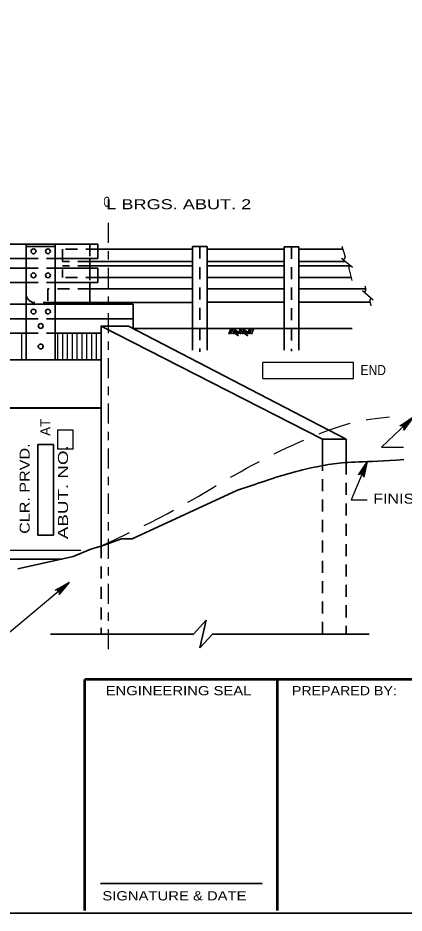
# Model space of a CAD drawing. Extents: x -11 to 79, y -154 to 0.
# Drawn here: x 11.68 to 16.3, y -43.25 to -32.54 of the extents above; entities that cross this region are included whole.
import ezdxf
from ezdxf.enums import TextEntityAlignment as Align

# ---------------------------------------------------------------- set-up
doc = ezdxf.new("R2010")
doc.units = 0
doc.header["$LTSCALE"] = 0.048
doc.linetypes.add('DOT_DASHED', pattern=[7.7, 5, -1.2, 0.3, -1.2])
doc.linetypes.add('MEDIUM_DASHED', pattern=[4.5, 3, -1.5])
for name, color, linetype, lineweight in [('1', 7, 'Continuous', 25), ('10', 7, 'Continuous', 40), ('3', 7, 'Continuous', 25), ('4', 7, 'Continuous', 25), ('5', 7, 'Continuous', 25), ('8', 7, 'Continuous', 35)]:
    doc.layers.add(name, color=color, linetype=linetype, lineweight=lineweight)

msp = doc.modelspace()

# ---------------------------------------------------------------- hatches: boundary and pattern name
at = {"layer": '3'}
msp.add_hatch(color=256, dxfattribs=at).paths.add_polyline_path([(15.79492, -37.95158), (15.83125, -37.96675), (15.85858, -37.85017)])
at = {"layer": '4'}
msp.add_hatch(color=256, dxfattribs=at).paths.add_polyline_path([(12.18967, -39.35475), (12.21492, -39.385), (12.293, -39.29417)])

# ---------------------------------------------------------------- linework, layer by layer
at = {"layer": '1', "lineweight": 35}
msp.add_lwpolyline([(1.75, -43.25), (33.25, -43.25), (33.25, -22.75), (1.75, -22.75)], close=True, dxfattribs=at)
at = {"layer": '3', "lineweight": 35}
for p, q in [((5.56042, -35.24708), (12.63733, -35.24708)), ((11.78058, -35.24708), (11.78058, -36.63125)), ((11.78058, -35.27592), (12.12658, -35.27592)), ((12.12658, -35.24708), (12.12658, -36.63125)), ((12.63733, -35.24708), (12.63733, -35.42008)), ((12.63733, -35.30808), (13.77008, -35.30808)), ((13.77008, -35.27758), (13.94308, -35.27758)), ((13.77008, -36.25633), (13.77008, -35.27758)), ((13.94308, -36.25633), (13.94308, -35.27758)), ((13.94308, -35.3095), (14.86583, -35.3095)), ((14.86583, -35.28067), (15.03883, -35.28067)), ((14.86583, -36.25633), (14.86583, -35.28067)), ((15.03883, -36.25633), (15.03883, -35.28067)), ((15.03883, -35.3095), (15.565, -35.3095)), ((10.22342, -35.42008), (11.78058, -35.42008)), ((12.12658, -35.42008), (12.63733, -35.42008)), ((12.54208, -35.42008), (12.54208, -35.5355)), ((10.22342, -35.5355), (11.78058, -35.5355)), ((12.12658, -35.5355), (12.63733, -35.5355)), ((12.54208, -35.45408), (13.77008, -35.45408)), ((12.54208, -35.50617), (13.77008, -35.50617)), ((12.63733, -35.5355), (12.63733, -35.7085)), ((13.94308, -35.45408), (14.86583, -35.45408)), ((13.94308, -35.50617), (14.86583, -35.50617)), ((15.03883, -35.45408), (15.59783, -35.45408)), ((15.03883, -35.50617), (15.65983, -35.50617)), ((12.63733, -35.6475), (13.77008, -35.6475)), ((13.94308, -35.6475), (14.86583, -35.6475)), ((15.03883, -35.6475), (15.666, -35.6475)), ((10.22342, -35.7085), (11.78058, -35.7085)), ((12.12658, -35.7085), (12.63733, -35.7085)), ((12.54208, -35.7085), (12.54208, -35.947)), ((12.54208, -35.78417), (13.77008, -35.78417)), ((13.94308, -35.78417), (14.86583, -35.78417)), ((15.03883, -35.78417), (15.84225, -35.78417)), ((10.22342, -35.968), (11.78058, -35.968)), ((11.78058, -35.968), (12.12658, -35.968)), ((12.12642, -35.947), (13.77008, -35.947)), ((12.12658, -35.968), (13.05858, -35.968)), ((13.05858, -36.25633), (13.05858, -35.968)), ((14.86583, -35.94242), (13.94308, -35.94242)), ((15.89208, -35.94242), (15.03883, -35.94242)), ((10.22342, -36.141), (11.78058, -36.141)), ((12.12658, -36.141), (13.05858, -36.141)), ((12.67467, -36.2275), (15.32283, -37.58275)), ((13.00317, -36.2275), (15.60825, -37.58275)), ((13.05858, -36.25633), (15.6805, -36.25633)), ((13.77008, -36.25633), (13.77008, -36.51583)), ((13.94308, -36.25633), (13.94308, -36.51583)), ((14.22942, -36.25633), (14.20275, -36.32658)), ((14.25133, -36.256), (14.22467, -36.32625)), ((14.27683, -36.25558), (14.25017, -36.32583)), ((14.265, -36.2865), (14.31667, -36.32225)), ((14.2715, -36.26933), (14.32308, -36.30517)), ((14.34192, -36.25558), (14.31567, -36.32483)), ((14.36383, -36.25542), (14.33758, -36.32442)), ((14.38917, -36.25517), (14.36308, -36.32408)), ((14.37742, -36.28608), (14.429, -36.32183)), ((14.38383, -36.26892), (14.4355, -36.30475)), ((14.45433, -36.25517), (14.42808, -36.32442)), ((14.47617, -36.255), (14.45, -36.32408)), ((14.50158, -36.25483), (14.4755, -36.32367)), ((14.86583, -36.25633), (14.86583, -36.51583)), ((15.03883, -36.25633), (15.03883, -36.51583)), ((10.22342, -36.314), (11.78058, -36.314)), ((12.12658, -36.314), (12.67467, -36.314)), ((12.67467, -36.4005), (12.67467, -38.86058)), ((14.25817, -36.30442), (14.31817, -36.346)), ((14.37058, -36.304), (14.43058, -36.34558)), ((5.52325, -36.63125), (12.67467, -36.63125)), ((15.32283, -37.58275), (15.60825, -37.58275)), ((15.32283, -37.89667), (15.32283, -37.58275)), ((15.60825, -37.58275), (15.60825, -37.86058)), ((14.30883, -38.19208), (13.04533, -38.77158)), ((13.04533, -38.77158), (12.91933, -38.77467)), ((5.77742, -39.016), (12.20667, -39.016)), ((13.77908, -39.91158), (13.93283, -39.74475)), ((13.93283, -39.74475), (13.85583, -40.0785)), ((12.07175, -39.91158), (13.77908, -39.91158)), ((13.85583, -40.0785), (14.00958, -39.91158)), ((14.00958, -39.91158), (15.88267, -39.91158))]:
    msp.add_line(p, q, dxfattribs=at)
at = {"layer": '3', "linetype": 'MEDIUM_DASHED', "lineweight": 35}
for p, q in [((12.63733, -35.30808), (12.21333, -35.30808)), ((12.21333, -35.30808), (12.21333, -35.6475)), ((12.54208, -35.24708), (12.54208, -35.42008)), ((13.85658, -35.27758), (13.85658, -36.53767)), ((14.95233, -35.28067), (14.95233, -36.52675)), ((11.78058, -35.42008), (12.12658, -35.42008)), ((11.78058, -35.5355), (12.12658, -35.5355)), ((12.54208, -35.45408), (12.21333, -35.45408)), ((12.54208, -35.50617), (12.21333, -35.50617)), ((12.54208, -35.5355), (12.54208, -35.7085)), ((12.63733, -35.6475), (12.21333, -35.6475)), ((11.78058, -35.7085), (12.12658, -35.7085)), ((12.12675, -35.947), (11.86333, -35.947)), ((11.78058, -36.141), (12.12658, -36.141)), ((11.78058, -36.314), (12.12658, -36.314)), ((15.32283, -39.91158), (15.32283, -37.89667)), ((15.60825, -37.86058), (15.60825, -39.91158)), ((12.67467, -38.86058), (12.67467, -39.91158))]:
    msp.add_line(p, q, dxfattribs=at)
at = {"layer": '3'}
for p, q in [((15.55342, -35.2735), (15.594, -35.39958)), ((15.55133, -35.41508), (15.68192, -35.52467)), ((15.63867, -35.53825), (15.67483, -35.68283)), ((15.83083, -35.74875), (15.84358, -35.78842)), ((15.80092, -35.80392), (15.9315, -35.9135)), ((15.88825, -35.92708), (15.90333, -35.9875)), ((5.52325, -36.63117), (12.67467, -36.63117)), ((16.40917, -37.31892), (16.02983, -37.67617)), ((16.02983, -37.67617), (16.29375, -37.67617)), ((15.85858, -37.85017), (15.66825, -38.30592)), ((15.66825, -38.30592), (15.85883, -38.30592))]:
    msp.add_line(p, q, dxfattribs=at)
at = {"layer": '3', "lineweight": 40}
msp.add_line((5.52325, -37.20783), (12.67467, -37.20783), dxfattribs=at)
at = {"layer": '3', "linetype": 'MEDIUM_DASHED', "lineweight": 35}
msp.add_lwpolyline([(12.54208, -35.78417), (12.0395, -35.78417), (12.0395, -35.947)], dxfattribs=at)
at = {"layer": '3', "lineweight": 35}
msp.add_lwpolyline([(12.67467, -36.4005), (12.67467, -36.2275), (13.00317, -36.2275)], dxfattribs=at)
at = {"layer": '3'}
msp.add_lwpolyline([(15.79492, -37.95158), (15.83125, -37.96675), (15.85858, -37.85017)], close=True, dxfattribs=at)
at = {"layer": '3', "lineweight": 35}
for centre in [(11.867, -35.33359), (12.04002, -35.33359), (11.867, -35.62194), (12.04002, -35.62194), (11.86699, -36.05451), (12.04, -36.05451), (11.9535, -36.22691), (11.95353, -36.472)]:
    msp.add_circle(centre, 0.02883, dxfattribs=at)
at = {"layer": '3'}
msp.add_circle((11.95353, -36.47195), 0.02883, dxfattribs=at)
for centre, start, end in [((15.57373, -35.40603), 227.85042, 17.85042), ((15.65947, -35.53355), 49.98318, 192.52183), ((15.65949, -35.5336), 49.98318, 49.99719), ((15.82331, -35.79486), 227.85042, 17.85042), ((15.90906, -35.92238), 49.98318, 192.52183), ((15.90907, -35.92243), 49.98318, 49.99719)]:
    msp.add_arc(centre, 0.02131, start, end, dxfattribs=at)
at = {"layer": '3', "linetype": 'MEDIUM_DASHED', "lineweight": 35}
msp.add_arc((11.89545, -35.83358), 0.1179, 193.19618, 254.16171, dxfattribs=at)
at = {"layer": '3', "lineweight": 35}
msp.add_open_spline([(14.30883, -38.19208), (14.62, -38.08475), (14.90592, -37.99158), (15.19175, -37.92175), (15.46175, -37.86933), (15.71583, -37.85192), (16.05733, -37.84608), (16.29558, -37.82275)], degree=3, dxfattribs=at)
at = {"layer": '4', "linetype": 'DOT_DASHED'}
msp.add_line((12.76092, -34.99267), (12.76092, -40.16842), dxfattribs=at)
at = {"layer": '4'}
for p, q in [((14.60825, -36.85342), (14.60825, -36.66525)), ((12.15275, -37.4725), (12.15275, -37.70242)), ((12.34092, -37.4725), (12.15275, -37.4725)), ((12.34092, -37.70242), (12.34092, -37.4725)), ((12.34092, -37.70242), (12.15275, -37.70242)), ((11.19925, -38.91042), (12.43233, -38.91042))]:
    msp.add_line(p, q, dxfattribs=at)
at = {"layer": '4', "lineweight": 35}
for p, q in [((11.91892, -37.64283), (11.91892, -38.72875)), ((12.10717, -37.64283), (11.91892, -37.64283)), ((12.10717, -38.72875), (12.10717, -37.64283)), ((12.10717, -38.72875), (11.91892, -38.72875)), ((14.60183, -42.89675), (12.66708, -42.89675))]:
    msp.add_line(p, q, dxfattribs=at)
at = {"layer": '4', "lineweight": 53}
for p, q in [((12.48275, -43.21967), (12.48275, -40.45567)), ((18.01075, -40.45567), (12.48275, -40.45567)), ((14.78617, -43.21967), (14.78617, -40.45567))]:
    msp.add_line(p, q, dxfattribs=at)
at = {"layer": '4'}
for points in [[(14.60825, -36.85342), (15.69417, -36.85342), (15.69417, -36.66525), (14.60825, -36.66525)], [(16.40917, -37.31892), (16.29742, -37.47217), (16.30108, -37.45508), (16.29792, -37.44092), (16.29083, -37.43033), (16.28075, -37.42267), (16.26675, -37.41867), (16.2495, -37.42125), (16.40917, -37.31892), (16.26675, -37.41867), (16.28075, -37.42267), (16.40917, -37.31892), (16.29083, -37.43033), (16.29792, -37.44092), (16.40917, -37.31892), (16.30108, -37.45508)], [(15.85858, -37.85017), (15.819, -38.03567), (15.81533, -38.01858), (15.80667, -38.00692), (15.796, -38.00008), (15.78358, -37.99725), (15.76925, -37.99933), (15.7545, -38.00875), (15.85858, -37.85017), (15.76925, -37.99933), (15.78358, -37.99725), (15.85858, -37.85017), (15.796, -38.00008), (15.80667, -38.00692), (15.85858, -37.85017), (15.81533, -38.01858)], [(12.293, -39.29417), (11.22725, -40.18325), (10.14683, -40.18325)], [(12.293, -39.29417), (12.17225, -39.44042), (12.17692, -39.42358), (12.17458, -39.40925), (12.16825, -39.39825), (12.15858, -39.39), (12.14483, -39.38517), (12.1275, -39.38675), (12.293, -39.29417), (12.14483, -39.38517), (12.15858, -39.39), (12.293, -39.29417), (12.16825, -39.39825), (12.17458, -39.40925), (12.293, -39.29417), (12.17692, -39.42358)]]:
    msp.add_lwpolyline(points, dxfattribs=at)
at = {"layer": '4', "lineweight": 35}
msp.add_lwpolyline([(11.68058, -39.13267), (12.34117, -38.98617), (12.55142, -38.89633), (12.70208, -38.85267), (12.91933, -38.77467)], dxfattribs=at)
at = {"layer": '4'}
msp.add_lwpolyline([(12.18967, -39.35475), (12.21492, -39.385), (12.293, -39.29417)], close=True, dxfattribs=at)
at = {"layer": '5'}
for p, q in [((11.72292, -36.314), (11.72292, -36.63117)), ((12.15558, -36.314), (12.15558, -36.63117)), ((12.21325, -36.314), (12.21325, -36.63117)), ((12.27092, -36.314), (12.27092, -36.63117)), ((12.32858, -36.314), (12.32858, -36.63117)), ((12.38625, -36.314), (12.38625, -36.63117)), ((12.44392, -36.314), (12.44392, -36.63117)), ((12.50158, -36.314), (12.50158, -36.63117)), ((12.55925, -36.314), (12.55925, -36.63117)), ((12.617, -36.314), (12.617, -36.63117))]:
    msp.add_line(p, q, dxfattribs=at)
at = {"layer": '8', "lineweight": 25}
for p, q in [((15.84792, -37.34942), (15.86125, -37.34692)), ((15.86125, -37.34692), (15.98508, -37.3295)), ((15.98508, -37.3295), (16.12608, -37.31525)), ((15.31325, -37.50625), (15.39625, -37.47442)), ((15.39625, -37.47442), (15.479, -37.44442)), ((15.479, -37.44442), (15.56375, -37.4165)), ((15.56375, -37.4165), (15.65367, -37.39067)), ((15.65367, -37.39067), (15.65542, -37.39025)), ((15.28325, -37.51817), (15.31325, -37.50625)), ((14.8105, -37.7255), (14.89342, -37.68625)), ((14.89342, -37.68625), (14.97708, -37.64783)), ((14.97708, -37.64783), (15.06117, -37.61058)), ((15.06117, -37.61058), (15.10133, -37.59333)), ((14.74383, -37.75808), (14.8105, -37.7255)), ((14.4155, -37.92933), (14.49108, -37.88842)), ((14.49108, -37.88842), (14.56842, -37.84733)), ((14.22358, -38.03725), (14.27142, -38.00983)), ((14.27142, -38.00983), (14.34225, -37.97)), ((14.34225, -37.97), (14.4155, -37.92933)), ((13.89717, -38.22917), (13.95683, -38.19383)), ((13.95683, -38.19383), (14.01608, -38.15867)), ((14.01608, -38.15867), (14.05358, -38.1365)), ((13.71392, -38.3355), (13.77217, -38.30217)), ((13.77217, -38.30217), (13.83608, -38.26508)), ((13.83608, -38.26508), (13.89717, -38.22917)), ((13.46433, -38.47325), (13.54192, -38.43142)), ((13.25667, -38.58075), (13.3665, -38.52467)), ((13.3665, -38.52467), (13.46433, -38.47325)), ((13.19242, -38.61258), (13.25667, -38.58075)), ((12.83575, -38.78375), (12.99325, -38.70967)), ((12.99325, -38.70967), (13.01558, -38.69892)), ((12.65867, -38.86517), (12.83575, -38.78375))]:
    msp.add_line(p, q, dxfattribs=at)

# ---------------------------------------------------------------- texts
at = {"layer": '10', "width": 1.2}
for s, p in [('ENGINEERING SEAL', (13.60225, -40.64458)), ('SIGNATURE & DATE', (13.55279, -43.09833))]:
    msp.add_text(s, height=0.1105, dxfattribs=at).set_placement(p, align=Align.CENTER)
at = {"layer": '10', "width": 1.15}
msp.add_text('PREPARED BY:', height=0.1105, dxfattribs=at).set_placement((14.95767, -40.64458))
at = {"layer": '4'}
for s, width, p in [('C', 0.65, (12.70375, -34.80108)), ('L BRGS. ABUT. 2', 1.35, (12.73817, -34.83083)), ('END', 0.9, (15.77817, -36.81392)), ('FINISH GRADE', 1.2, (15.93025, -38.3525))]:
    msp.add_text(s, height=0.12, dxfattribs=dict(at, width=width)).set_placement(p)
msp.add_text('AT', height=0.12, rotation=90, dxfattribs=at).set_placement((12.06933, -37.54108))
for s, width, p in [('CLR. PRVD.', 1.2, (11.82133, -38.71308)), ('ABUT. NO. ', 1.4, (12.27967, -38.777))]:
    msp.add_text(s, height=0.12, rotation=90, dxfattribs=dict(at, width=width)).set_placement(p)

doc.saveas('drawing.dxf')
